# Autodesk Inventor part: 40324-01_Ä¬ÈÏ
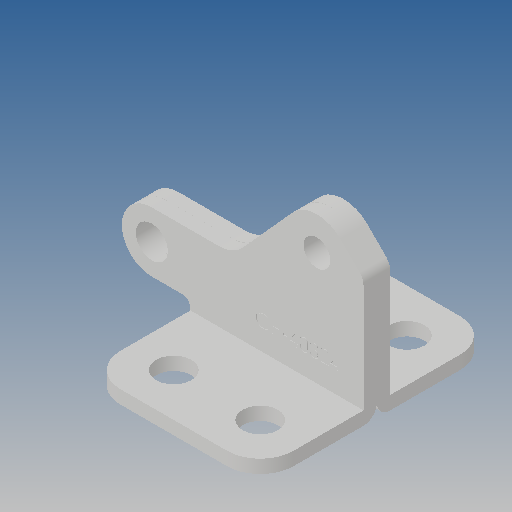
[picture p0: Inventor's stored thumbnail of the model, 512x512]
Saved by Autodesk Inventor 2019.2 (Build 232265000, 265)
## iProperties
Created: 2010-06
Part Number: 40324-01_Ä¬ÈÏ
Material: Ogólny
Document SubType Name: Modeling
Designer: CADENGINEERING4
Density: 1 g/cm^3
Appearance: Domyślna
Author: CADENGINEERING4
Revision Number: ÈÎºÎ
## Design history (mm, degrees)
feature "NONE"
feature "NONE:1"
node "Bryła1"
node "Bryła2"
